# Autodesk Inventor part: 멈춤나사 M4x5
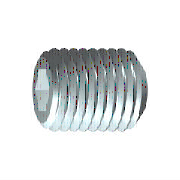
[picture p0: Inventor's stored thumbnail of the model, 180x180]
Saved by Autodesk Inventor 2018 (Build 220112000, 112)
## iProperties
IsCustomPart: 1
Created: 2012-02
Part Number: 멈춤나사 M4x5
Material: 강철, 연강
Description: 6각 소켓 머리 없는 멈춤 나사
Document SubType Name: Modeling
Standard: KS B 1028
Designer: mduedu
Standards Organization: KS
Language: ko-KR
Size Designation: 납작점M4x5
Categories: <MemberInstance><Categories><Category DisplayName="조임쇠" InternalName="e4da775c-781d-43d5-af7c-5136215cf5a6" Mnemonic="FSTN"><Category DisplayName="볼트" InternalN
Density: 1 g/cm^3
Appearance: Steel
Author: mduedu
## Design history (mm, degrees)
sketch "스케치1"
  geometry: L1 (0, 0)-(1.833, 0); L2 (5, 1.155)-(5, 2); L3 (5, 2)-(0, 2); L4 (5, 1.155)-(2.5, 1.155); L5 (2.5, 1.155)-(1.833, 0); L6 (0, -0.4)-(0, 2.4) reference; L7 (0, 2)-(0, 0)
  constraints: 13 end point, 3 parallel, 1 collinear, 1 perpendicular, 1 point on line
  dimensions: "d0" = 2.5 distance of L2.start L4.end (= INTI); "d1" = 60 deg angle of L5 L1; "d2" = 4 diameter of L3 L1 (= NND); "d3" = 2.3094 diameter of L4 L1 (= 1.1547 x SW); "d5" = 5 distance from line of L2 L3.end (= NLG)
revolve "본체" sketch "스케치1" stored, may be unused: angle "d6" = 90 deg
sketch "스케치2"
  geometry: L1 (-0.577, 1)-(0.577, 1); L2 (0.577, 1)-(1.155, 0); L3 (1.155, 0)-(0.577, -1); L4 (0.577, -1)-(-0.577, -1); L5 (-0.577, -1)-(-1.155, 0); L6 (-1.155, 0)-(-0.577, 1); A1 r 1.155 centre (0, 0) between (-0.577, 1) and (0.577, 1) reference; 2 further points
  constraints: 12 end point, 2 point on circle, 1 coincident, 1 horizontal, 11 other
extrude "슬롯" join sketch "스케치2" taper "d9" = 0 deg; stored distance "d21" = 10
workaxis "Work Axis1"
workplane "Work Plane1"
body "Solid1"
chamfer "모따기1" distance "d7" = 0.42941 (= -0.5 x GD1 + 0.5 x NND); stored, may be unused: angle "d8" = 45 deg (= FAWI), second distance "d29" = 0.42941 (= -0.5 x GD1 + 0.5 x NND)
feature "스레드" dims "d11" = 5 (= NLG), "d12" = 0
chamfer "모따기2" distance "d13" = 0.42941 (= -0.5 x GD1 + 0.5 x NND); stored, may be unused: angle "d14" = 45 deg (= FAWI), second distance "d30" = 0.42941 (= -0.5 x GD1 + 0.5 x NND)
other parameters: "NND" = 4 [user parameter; used in 5 equation terms], "NLG" = 5 [user parameter; used in 2 equation terms], "INTI" = 2.5 [user parameter; used in 1 equation term], "FAWI" = 45 deg [user parameter; used in 2 equation terms], "SW" = 2 [user parameter; used in 2 equation terms], "GD1" = 3.14117 (= THREADDIA - 1.2269 x PTC) [user parameter; used in 4 equation terms], "d4" = 0, "FAWI1" = 45 deg [user parameter], "d15" = 0, "d31" = 0, "GUL" = 0.42941 (= 0.61345 x PTC) [user parameter], "SPD" = 2.5 [user parameter], "TPU" = 14.28571 (computed from PTC) [user parameter], "TOA" = 30 deg [user parameter], "THREADDIA" = 4 [user parameter; used in 1 equation term], "PTC" = 0.7 [user parameter; used in 4 equation terms], "GAL" = 0.42941 (= 0.61345 x PTC) [user parameter], "E0" = 2.31 (= 1.155 x SW) [user parameter]
